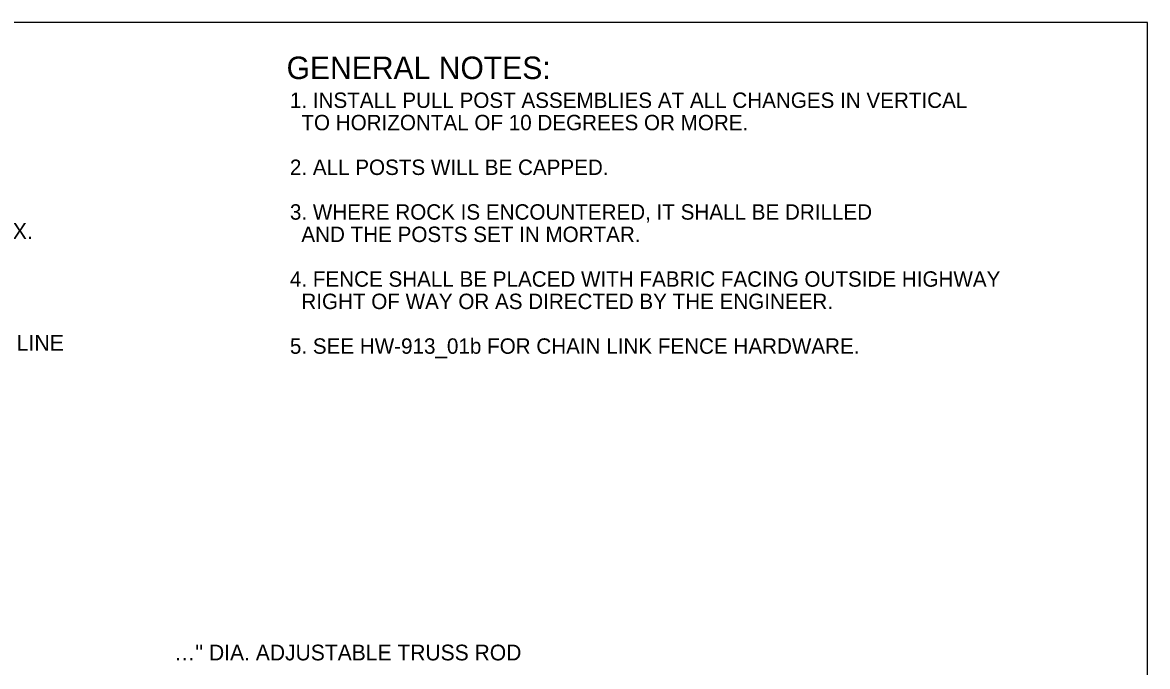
# Model space of a CAD drawing. Extents: x 0 to 1270, y 0 to 830.
# Drawn here: x 919.9 to 1270, y 629.4 to 830 of the extents above; entities that cross this region are included whole.
import ezdxf

# ---------------------------------------------------------------- set-up
doc = ezdxf.new("R2010")
doc.units = 0
for name, color, linetype in [('CT_Border_Perimeter_Shape', 7, 'Continuous'), ('CT_CSHT_GeneralLabel', 7, 'Continuous'), ('CT_Dimensions', 7, 'Continuous'), ('CT_Title_Block_Text', 7, 'Continuous')]:
    doc.layers.add(name, color=color, linetype=linetype)

# ---------------------------------------------------------------- blocks, each defined once
blk = doc.blocks.new('BDR_CTDOT_Standards')
at = {"layer": 'CT_Border_Perimeter_Shape'}
blk.add_lwpolyline([(0, 0), (1270, 0), (1270, 830), (0, 830)], close=True, dxfattribs=at)

msp = doc.modelspace()

# ---------------------------------------------------------------- block references
at = {"layer": 'CT_Title_Block_Text'}
msp.add_blockref('BDR_CTDOT_Standards', (0, 0), dxfattribs=at)

# ---------------------------------------------------------------- texts
at = {"layer": 'CT_CSHT_GeneralLabel'}
msp.add_text('GENERAL NOTES:', height=7, dxfattribs=at).set_placement((1002.06, 812.38))
at = {"layer": 'CT_Dimensions'}
for s, height, p in [('1. INSTALL PULL POST ASSEMBLIES AT ALL CHANGES IN VERTICAL', 4.8, (1003.09, 803.39)), ('  TO HORIZONTAL OF 10 DEGREES OR MORE.', 4.8, (1003.09, 796.43)), ('2. ALL POSTS WILL BE CAPPED.', 4.8, (1003.09, 782.51)), ('3. WHERE ROCK IS ENCOUNTERED, IT SHALL BE DRILLED ', 4.8, (1003.09, 768.59)), ("2'' APPROX.", 4.95, (885.6, 762.57)), ('  AND THE POSTS SET IN MORTAR.', 4.8, (1003.09, 761.63)), ('4. FENCE SHALL BE PLACED WITH FABRIC FACING OUTSIDE HIGHWAY ', 4.8, (1003.09, 747.71)), ('  RIGHT OF WAY OR AS DIRECTED BY THE ENGINEER.', 4.8, (1003.09, 740.75)), ('GROUND LINE', 4.95, (886.77, 727.77)), ('5. SEE HW-913_01b FOR CHAIN LINK FENCE HARDWARE.', 4.8, (1003.09, 726.83)), ("…'' DIA. ADJUSTABLE TRUSS ROD", 4.9005, (967.03, 631.34))]:
    msp.add_text(s, height=height, dxfattribs=at).set_placement(p)

doc.saveas('drawing.dxf')
